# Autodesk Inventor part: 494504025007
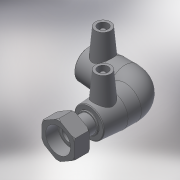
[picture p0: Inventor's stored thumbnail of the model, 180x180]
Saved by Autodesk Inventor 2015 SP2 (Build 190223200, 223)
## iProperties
Created: 2017-06
Part Number: 494504025007
Material: Generic
Description: PLASSON 90° ELBOW FEMALE FREE NUT TRANSITION 25-3/4"
Document SubType Name: Modeling
Designer: KIM
Mass: 55.0731 g
Surface Area: 148.067 cm^2
Volume: 55.0731 cm^3
Density: 1 g/cm^3
Appearance: Default
Author: KIM
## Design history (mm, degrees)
derived "494504.ipt"
feature "Solid1::494504.ipt"
tag "TaggingFeature1"
body "Solid1"
other parameters: "d2" = 36, "d4" = 22, "d5" = 32.4, "d8" = 168 deg, "d10" = 14.8, "d11" = 4.93333, "d29" = 38, "d30" = 15, "d31" = 36.3, "d34" = 5 deg, "d41" = 4, "d42" = 14, "d43" = 0, "d48" = 48, "d49" = 25, "d50" = 21.25, "d51" = 14.8, "d52" = 37, "d54" = 90 deg, "d57" = 25, "d58" = 37, "d59" = 0, "d61" = 90 deg, "d86" = 3, "d87" = 0, "d97" = 14, "d99" = 36.1755, "d109" = 0.75, "d116" = 15, "d117" = 24.117, "d118" = 12, "d119" = 1.2, "d120" = 19.2936, "d121" = 1.2, "d122" = 16.8819, "d123" = 14, "d124" = 1.20585, "d128" = 0, "d_" = 25, "L_" = 96, "L_1" = 37, "D_" = 14, "A_" = 38, "d_2" = 12, "D_1" = 36, "G_" = 24.117
